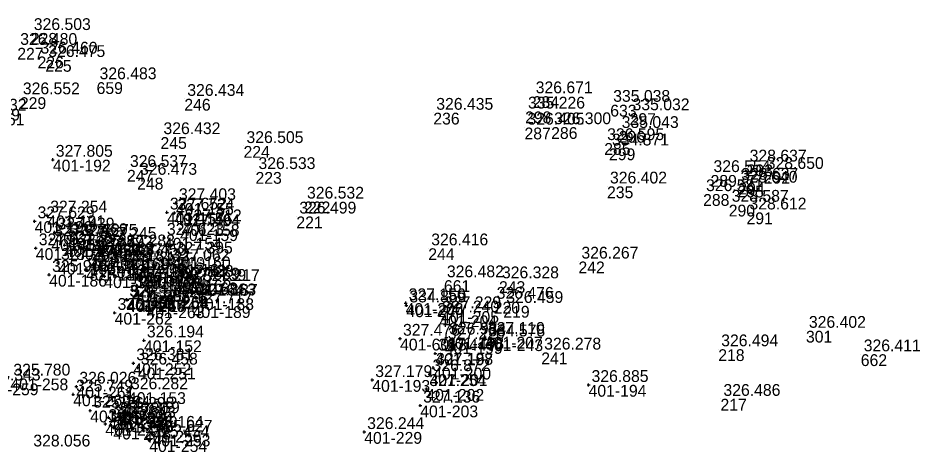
# Model space of a CAD drawing. Extents: x -829398 to -819400, y -1074439 to -1067977.
# Drawn here: x -823946.7 to -823854.9, y -1070097.7 to -1070053.9 of the extents above; entities that cross this region are included whole.
import ezdxf

# ---------------------------------------------------------------- set-up
doc = ezdxf.new("R2010")
doc.units = 0
for name, color, linetype in [('Vrstva 60', 7, 'Continuous'), ('Vrstva 61', 7, 'Continuous'), ('Čísla bodů_doměření_2012', 7, 'Continuous')]:
    doc.layers.add(name, color=color, linetype=linetype)

# ---------------------------------------------------------------- blocks, each defined once
blk = doc.blocks.new('BOD')
at = {"layer": 'Čísla bodů_doměření_2012'}
for p, q in [((-0.15, 0), (0.15, 0)), ((0, -0.15), (0, 0.15))]:
    blk.add_line(p, q, dxfattribs=at)

msp = doc.modelspace()

# ---------------------------------------------------------------- linework, layer by layer
at = {"layer": 'Vrstva 60'}
for p, q in [((-823945.397, -1070055.44), (-823945.397, -1070055.44)), ((-823944.711, -1070057.838), (-823944.711, -1070057.838)), ((-823943.925, -1070058.184), (-823943.925, -1070058.184)), ((-823938.705, -1070060.45), (-823938.705, -1070060.45)), ((-823946.511, -1070061.98), (-823946.511, -1070061.98)), ((-823929.776, -1070062.142), (-823929.776, -1070062.142)), ((-823894.32, -1070061.876), (-823894.32, -1070061.876)), ((-823886.433, -1070062.745), (-823886.433, -1070062.745)), ((-823904.438, -1070063.553), (-823904.438, -1070063.553)), ((-823895.101, -1070063.428), (-823895.101, -1070063.428)), ((-823884.462, -1070063.604), (-823884.462, -1070063.604)), ((-823895.16, -1070065.066), (-823895.16, -1070065.066)), ((-823892.447, -1070065.02), (-823892.447, -1070065.02)), ((-823932.202, -1070066.035), (-823932.202, -1070066.035)), ((-823885.567, -1070065.407), (-823885.567, -1070065.407)), ((-823923.753, -1070066.94), (-823923.753, -1070066.94)), ((-823887.045, -1070066.64), (-823887.045, -1070066.64)), ((-823886.56, -1070067.188), (-823886.56, -1070067.188)), ((-823872.546, -1070068.816), (-823872.546, -1070068.816)), ((-823935.612, -1070069.371), (-823935.612, -1070069.371)), ((-823922.535, -1070069.585), (-823922.535, -1070069.585)), ((-823870.808, -1070069.572), (-823870.808, -1070069.572)), ((-823934.579, -1070070.169), (-823934.579, -1070070.169)), ((-823876.228, -1070069.892), (-823876.228, -1070069.892)), ((-823873.398, -1070070.675), (-823873.398, -1070070.675)), ((-823886.759, -1070071.053), (-823886.759, -1070071.053)), ((-823873.476, -1070070.974), (-823873.476, -1070070.974)), ((-823876.983, -1070071.832), (-823876.983, -1070071.832)), ((-823917.595, -1070072.589), (-823917.595, -1070072.589)), ((-823874.372, -1070072.911), (-823874.372, -1070072.911)), ((-823918.375, -1070074.112), (-823918.375, -1070074.112)), ((-823872.563, -1070073.697), (-823872.563, -1070073.697)), ((-823904.951, -1070077.348), (-823904.951, -1070077.348)), ((-823889.667, -1070078.694), (-823889.667, -1070078.694)), ((-823903.357, -1070080.595), (-823903.357, -1070080.595)), ((-823897.755, -1070080.699), (-823897.755, -1070080.699)), ((-823898.29, -1070082.783), (-823898.29, -1070082.783)), ((-823897.314, -1070083.207), (-823897.314, -1070083.207)), ((-823866.516, -1070085.739), (-823866.516, -1070085.739)), ((-823893.456, -1070087.948), (-823893.456, -1070087.948)), ((-823875.441, -1070087.619), (-823875.441, -1070087.619)), ((-823860.936, -1070088.128), (-823860.936, -1070088.128)), ((-823875.214, -1070092.662), (-823875.214, -1070092.662))]:
    msp.add_line(p, q, dxfattribs=at)

# ---------------------------------------------------------------- block references
for p in [(-823943.158, -1070068.334), (-823930.627, -1070072.745), (-823943.724, -1070074.002), (-823931.546, -1070073.7), (-823930.779, -1070073.756), (-823945.011, -1070074.592), (-823930.206, -1070075.409), (-823930.043, -1070074.896), (-823942.983, -1070075.734), (-823941.631, -1070076.308), (-823931.847, -1070076.281), (-823943.312, -1070076.421), (-823941.96, -1070077.025), (-823940.648, -1070076.392), (-823938.709, -1070076.692), (-823944.893, -1070077.336), (-823939.085, -1070077.563), (-823936.836, -1070077.452), (-823942.623, -1070078.827), (-823939.422, -1070078.472), (-823937.178, -1070078.342), (-823935.652, -1070078.376), (-823931.286, -1070078.938), (-823930.953, -1070078.18), (-823939.783, -1070079.442), (-823937.549, -1070079.184), (-823935.388, -1070079.712), (-823935.161, -1070079.163), (-823933.786, -1070079.744), (-823943.538, -1070080.045), (-823937.918, -1070080.193), (-823934.021, -1070080.285), (-823930.876, -1070080.553), (-823930.243, -1070080.829), (-823935.094, -1070081.563), (-823935.051, -1070081.614), (-823929.58, -1070080.959), (-823928.203, -1070080.979), (-823935.674, -1070082.559), (-823935.584, -1070082.62), (-823934.505, -1070082.644), (-823933.219, -1070082.226), (-823933.219, -1070082.293), (-823928.578, -1070082.435), (-823933.62, -1070083.257), (-823928.927, -1070083.236), (-823907.251, -1070082.926), (-823907.172, -1070083.155), (-823936.869, -1070083.915), (-823903.837, -1070084.171), (-823903.643, -1070083.744), (-823903.126, -1070086.413), (-823899.195, -1070086.353), (-823933.887, -1070086.715), (-823907.823, -1070086.542), (-823903.266, -1070086.887), (-823899.152, -1070086.606), (-823904.234, -1070088.054), (-823934.965, -1070089.041), (-823934.506, -1070089.482), (-823904.453, -1070089.495), (-823910.648, -1070090.748), (-823904.816, -1070090.147), (-823940.763, -1070091.416), (-823905.148, -1070091.663), (-823888.636, -1070091.247), (-823941.088, -1070092.213), (-823935.507, -1070091.99), (-823905.77, -1070093.345), (-823939.358, -1070093.86), (-823937.506, -1070094.559), (-823936.893, -1070093.978), (-823936.352, -1070094.418), (-823937.813, -1070095.218), (-823937, -1070095.593), (-823936.754, -1070094.899), (-823933.908, -1070095.908), (-823933.013, -1070096.303), (-823911.47, -1070096.036), (-823933.343, -1070096.873)]:
    msp.add_blockref('BOD', p, dxfattribs=at)

# ---------------------------------------------------------------- texts
for s, p in [('228', (-823945.397, -1070056.64)), ('227', (-823946.778, -1070058.153)), ('226', (-823944.711, -1070059.038)), ('225', (-823943.925, -1070059.384)), ('659', (-823938.705, -1070061.65)), ('229', (-823946.511, -1070063.18)), ('246', (-823929.776, -1070063.342)), ('284', (-823894.32, -1070063.076)), ('633', (-823886.433, -1070063.945)), ('401-361', (-823951.937, -1070064.836)), ('236', (-823904.438, -1070064.753)), ('298', (-823895.101, -1070064.628)), ('297', (-823884.462, -1070064.804)), ('287', (-823895.16, -1070066.266)), ('286', (-823892.447, -1070066.22)), ('245', (-823932.202, -1070067.235)), ('296', (-823885.567, -1070066.607)), ('224', (-823923.753, -1070068.14)), ('285', (-823887.045, -1070067.84)), ('299', (-823886.56, -1070068.388)), ('401-192', (-823943.158, -1070069.534)), ('293', (-823872.546, -1070070.016)), ('247', (-823935.612, -1070070.571)), ('223', (-823922.535, -1070070.785)), ('292', (-823870.808, -1070070.772)), ('248', (-823934.579, -1070071.369)), ('289', (-823876.228, -1070071.092)), ('294', (-823873.398, -1070071.875)), ('235', (-823886.759, -1070072.253)), ('295', (-823873.476, -1070072.174)), ('288', (-823876.983, -1070073.032)), ('401-155', (-823930.627, -1070073.945)), ('222', (-823917.595, -1070073.789)), ('290', (-823874.372, -1070074.111)), ('401-191', (-823943.724, -1070075.202)), ('401-157', (-823931.546, -1070074.9)), ('401-156', (-823930.779, -1070074.956)), ('221', (-823918.375, -1070075.312)), ('291', (-823872.563, -1070074.897)), ('401-190', (-823945.011, -1070075.792)), ('401-158', (-823930.043, -1070076.096)), ('401-176', (-823942.983, -1070076.934)), ('401-159', (-823930.206, -1070076.609)), ('401-177', (-823943.312, -1070077.621)), ('401-178', (-823941.96, -1070078.225)), ('401-175', (-823941.631, -1070077.508)), ('401-179', (-823940.648, -1070077.592)), ('401-182', (-823938.709, -1070077.892)), ('401-154', (-823931.847, -1070077.481)), ('401-180', (-823944.893, -1070078.536)), ('401-170', (-823939.085, -1070078.763)), ('401-181', (-823936.836, -1070078.652)), ('244', (-823904.951, -1070078.548)), ('401-185', (-823942.623, -1070080.027)), ('401-171', (-823939.422, -1070079.672)), ('401-169', (-823937.178, -1070079.542)), ('401-173', (-823935.652, -1070079.576)), ('401-161', (-823931.286, -1070080.138)), ('401-160', (-823930.953, -1070079.38)), ('242', (-823889.667, -1070079.894)), ('401-183', (-823939.783, -1070080.642)), ('401-172', (-823937.549, -1070080.384)), ('401-167', (-823935.388, -1070080.912)), ('401-166', (-823935.161, -1070080.363)), ('401-165', (-823933.786, -1070080.944)), ('401-186', (-823943.538, -1070081.245)), ('401-184', (-823937.918, -1070081.393)), ('401-168', (-823934.021, -1070081.485)), ('401-162', (-823930.876, -1070081.753)), ('661', (-823903.357, -1070081.795)), ('243', (-823897.755, -1070081.899)), ('401-268', (-823935.094, -1070082.763)), ('401-265', (-823935.051, -1070082.814)), ('401-163', (-823930.243, -1070082.029)), ('401-164', (-823929.58, -1070082.159)), ('401-187', (-823928.203, -1070082.179)), ('401-267', (-823935.674, -1070083.759)), ('401-266', (-823935.584, -1070083.82)), ('401-269', (-823933.219, -1070083.426)), ('401-264', (-823933.219, -1070083.493)), ('401-188', (-823928.578, -1070083.635)), ('401-174', (-823934.505, -1070083.844)), ('401-263', (-823933.62, -1070084.457)), ('401-189', (-823928.927, -1070084.436)), ('401-206', (-823907.251, -1070084.126)), ('401-244', (-823907.172, -1070084.355)), ('220', (-823898.29, -1070083.983)), ('219', (-823897.314, -1070084.407)), ('401-262', (-823936.869, -1070085.115)), ('401-204', (-823903.837, -1070085.371)), ('401-205', (-823903.643, -1070084.944)), ('301', (-823866.516, -1070086.939)), ('401-152', (-823933.887, -1070087.915)), ('401-6013', (-823907.823, -1070087.742)), ('401-199', (-823903.266, -1070088.087)), ('401-198', (-823903.126, -1070087.613)), ('401-207', (-823899.195, -1070087.553)), ('401-243', (-823899.152, -1070087.806)), ('401-197', (-823904.234, -1070089.254)), ('241', (-823893.456, -1070089.148)), ('218', (-823875.441, -1070088.819)), ('662', (-823860.936, -1070089.328)), ('401-252', (-823934.965, -1070090.241)), ('401-251', (-823934.506, -1070090.682)), ('401-200', (-823904.453, -1070090.695)), ('401-258', (-823947.481, -1070091.798)), ('401-193', (-823910.648, -1070091.948)), ('401-201', (-823904.816, -1070091.347)), ('401-259', (-823950.502, -1070092.299)), ('401-261', (-823940.763, -1070092.616)), ('401-202', (-823905.148, -1070092.863)), ('401-194', (-823888.636, -1070092.447)), ('401-260', (-823941.088, -1070093.413)), ('401-153', (-823935.507, -1070093.19)), ('217', (-823875.214, -1070093.862)), ('401-203', (-823905.77, -1070094.545)), ('401-257', (-823939.358, -1070095.06)), ('401-250', (-823936.893, -1070095.178)), ('401-249', (-823936.352, -1070095.618)), ('401-247', (-823937.813, -1070096.418)), ('401-246', (-823937.506, -1070095.759)), ('401-245', (-823936.754, -1070096.099)), ('401-248', (-823937, -1070096.793)), ('401-256', (-823933.908, -1070097.108)), ('401-253', (-823933.013, -1070097.503)), ('401-229', (-823911.47, -1070097.236)), ('401-254', (-823933.343, -1070098.073))]:
    msp.add_text(s, height=1.2, dxfattribs=at).set_placement(p)
at = {"layer": 'Vrstva 61'}
for s, p in [('326.503', (-823945.097, -1070055.14)), ('326.480', (-823946.478, -1070056.653)), ('326.460', (-823944.411, -1070057.538)), ('326.475', (-823943.625, -1070057.884)), ('326.483', (-823938.405, -1070060.15)), ('326.552', (-823946.211, -1070061.68)), ('326.671', (-823894.02, -1070061.576)), ('326.434', (-823929.476, -1070061.842)), ('335.038', (-823886.133, -1070062.445)), ('327.432', (-823951.637, -1070063.336)), ('326.435', (-823904.138, -1070063.253)), ('335.226', (-823894.801, -1070063.128)), ('335.032', (-823884.162, -1070063.304)), ('327.679', (-823952.298, -1070064.348)), ('326.405', (-823894.86, -1070064.766)), ('326.300', (-823892.147, -1070064.72)), ('335.043', (-823885.267, -1070065.107)), ('326.432', (-823931.902, -1070065.735)), ('326.595', (-823886.745, -1070066.34)), ('326.505', (-823923.453, -1070066.64)), ('334.871', (-823886.26, -1070066.888)), ('327.805', (-823942.858, -1070068.034)), ('326.537', (-823935.312, -1070069.071)), ('328.637', (-823872.246, -1070068.516)), ('326.473', (-823934.279, -1070069.869)), ('326.533', (-823922.235, -1070069.285)), ('326.554', (-823875.928, -1070069.592)), ('328.650', (-823870.508, -1070069.272)), ('326.402', (-823886.459, -1070070.753)), ('328.640', (-823873.176, -1070070.674)), ('328.637', (-823873.098, -1070070.375)), ('326.581', (-823876.683, -1070071.532)), ('327.403', (-823930.327, -1070072.445)), ('326.532', (-823917.295, -1070072.289)), ('328.587', (-823874.072, -1070072.611)), ('327.254', (-823943.424, -1070073.702)), ('327.652', (-823931.246, -1070073.4)), ('327.724', (-823930.479, -1070073.456)), ('328.612', (-823872.263, -1070073.397)), ('327.629', (-823944.711, -1070074.292)), ('327.212', (-823929.743, -1070074.596)), ('326.499', (-823918.075, -1070073.812)), ('327.439', (-823942.683, -1070075.434)), ('327.404', (-823929.906, -1070075.109)), ('327.577', (-823943.012, -1070076.121)), ('327.469', (-823941.331, -1070076.008)), ('327.275', (-823940.348, -1070076.092)), ('327.245', (-823938.409, -1070076.392)), ('327.623', (-823931.547, -1070075.981)), ('327.532', (-823944.593, -1070077.036)), ('327.553', (-823941.66, -1070076.725)), ('327.592', (-823938.785, -1070077.263)), ('327.288', (-823936.536, -1070077.152)), ('326.416', (-823904.651, -1070077.048)), ('327.600', (-823939.122, -1070078.172)), ('327.577', (-823936.878, -1070078.042)), ('327.450', (-823935.352, -1070078.076)), ('327.395', (-823930.653, -1070077.88)), ('327.255', (-823942.323, -1070078.527)), ('327.127', (-823939.483, -1070079.142)), ('327.618', (-823937.249, -1070078.884)), ('327.431', (-823934.861, -1070078.863)), ('327.062', (-823930.986, -1070078.638)), ('326.267', (-823889.367, -1070078.394)), ('325.966', (-823943.238, -1070079.745)), ('327.181', (-823937.618, -1070079.893)), ('327.481', (-823935.088, -1070079.412)), ('327.485', (-823933.721, -1070079.985)), ('327.510', (-823933.486, -1070079.444)), ('327.828', (-823930.576, -1070080.253)), ('327.859', (-823929.943, -1070080.529)), ('327.739', (-823929.28, -1070080.659)), ('327.217', (-823927.903, -1070080.679)), ('326.482', (-823903.057, -1070080.295)), ('326.328', (-823897.455, -1070080.399)), ('327.361', (-823934.794, -1070081.263)), ('326.173', (-823934.751, -1070081.314)), ('327.357', (-823932.919, -1070081.926)), ('327.184', (-823935.374, -1070082.259)), ('326.198', (-823935.284, -1070082.32)), ('326.212', (-823934.205, -1070082.344)), ('326.210', (-823932.919, -1070081.993)), ('327.863', (-823928.278, -1070082.135)), ('327.156', (-823906.951, -1070082.626)), ('334.859', (-823906.872, -1070082.855)), ('326.476', (-823897.99, -1070082.483)), ('326.459', (-823897.014, -1070082.907)), ('326.053', (-823936.569, -1070083.615)), ('326.176', (-823933.32, -1070082.957)), ('327.717', (-823928.627, -1070082.936)), ('327.229', (-823903.343, -1070083.444)), ('327.240', (-823903.537, -1070083.871)), ('326.402', (-823866.216, -1070085.439)), ('326.194', (-823933.587, -1070086.415)), ('327.476', (-823907.523, -1070086.242)), ('326.984', (-823902.826, -1070086.113)), ('327.110', (-823898.895, -1070086.053)), ('334.578', (-823898.852, -1070086.306)), ('327.220', (-823902.966, -1070086.587)), ('326.494', (-823875.141, -1070087.319)), ('327.447', (-823903.934, -1070087.754)), ('326.278', (-823893.156, -1070087.648)), ('326.411', (-823860.636, -1070087.828)), ('326.381', (-823934.665, -1070088.741)), ('326.458', (-823934.206, -1070089.182)), ('327.188', (-823904.153, -1070089.195)), ('326.872', (-823904.516, -1070089.847)), ('326.343', (-823950.202, -1070090.799)), ('325.780', (-823947.181, -1070090.298)), ('326.026', (-823940.463, -1070091.116)), ('327.179', (-823910.348, -1070090.448)), ('326.885', (-823888.336, -1070090.947)), ('325.749', (-823940.788, -1070091.913)), ('326.282', (-823935.207, -1070091.69)), ('327.254', (-823904.848, -1070091.363)), ('326.486', (-823874.914, -1070092.362)), ('325.724', (-823939.058, -1070093.56)), ('326.298', (-823936.593, -1070093.678)), ('327.136', (-823905.47, -1070093.045)), ('325.780', (-823937.206, -1070094.259)), ('325.843', (-823936.454, -1070094.599)), ('326.359', (-823936.052, -1070094.118)), ('325.652', (-823937.513, -1070094.918)), ('325.844', (-823936.7, -1070095.293)), ('326.164', (-823933.608, -1070095.608)), ('326.244', (-823911.17, -1070095.736)), ('325.454', (-823933.043, -1070096.573)), ('325.627', (-823932.713, -1070096.003)), ('328.056', (-823945.145, -1070097.513))]:
    msp.add_text(s, height=1.2, dxfattribs=at).set_placement(p)

doc.saveas('drawing.dxf')
